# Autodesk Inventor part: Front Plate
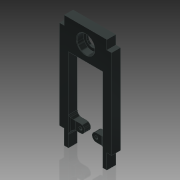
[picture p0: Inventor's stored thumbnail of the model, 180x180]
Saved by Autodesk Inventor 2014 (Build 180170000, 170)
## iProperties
Created: 2015-07
Part Number: Front Plate
Material: Generic
Document SubType Name: Modeling
Designer: Brad Factor
Density: 1 g/cm^3
Appearance: Gunmetal - Polished
Author: Brad Factor
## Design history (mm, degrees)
sketch "Sketch1"
  geometry: L1 (-8.509, 15.278)-(8.509, 15.278); L2 (-18.453, 83.414)-(18.453, 83.414); L3 (18.453, 83.414)-(18.453, 0); L4 (18.453, 0)-(27.978, 0); L5 (27.978, 0)-(27.978, 115.418); L6 (27.978, 115.418)-(-27.978, 115.418); L7 (-27.978, 115.418)-(-27.978, 0); L8 (-27.978, 0)-(-18.453, 0); L9 (-18.453, 0)-(-18.453, 83.414); L10 (-27.978, 109.068)-(27.978, 109.068); L11 (-27.978, 89.764)-(27.978, 89.764); C1 r 9.652 at (0, 99.416); C2 r 1.27 at (8.509, 15.278); C3 r 1.27 at (-8.509, 15.278); C4 r 9.588 at (0, 99.416); A1 r 12.103 centre (0, 15.278) between (0, 3.175) and (-12.103, 15.278); 3 further points
  constraints: 22 end point, 7 horizontal, 5 centre point, 5 point on line, 4 vertical, 3 horizontal alignment, 3 point on circle, 3 vertical alignment, 2 coincident, 2 tangent, 1 midpoint
  dimensions: "d0" = 24.2062 diameter of A1; "d1" = 3.175 distance of A1.start point (0, 0); "d2" = 19.304 diameter of C1; "d3" = 84.1375 distance of A1.centre C1.centre; "d4" = 2.54 diameter of C2; "d5" = 2.54 diameter of C3; "d6" = 17.018 distance of L1.end L1.start; "d7" = 6.35 distance from line of A1.end L9; "d8" = 6.35 distance from line of point (12.103, 15.278) L3; "d9" = 6.35 distance between parallel lines of L6 L10; "d10" = 6.35 distance between parallel lines of L11 L2; "d11" = 9.525 distance between parallel lines of L7 L9; "d12" = 9.525 distance between parallel lines of L5 L3; "d46" = 19.177 diameter of C4
extrude "Plate" new body sketch "Sketch1" distance "d13" = 9.525; taper "d14" = 0 deg
sketch "Sketch3"
  geometry: C1 r 9.588 at (0, 99.416); C2 r 6.413 at (0, 99.416); C3 r 9.588 at (0, 99.416) reference; 1 further point
  constraints: 2 centre point, 1 coincident, 1 concentric
  dimensions: "d47" = 3.175 radial gap between concentric circles of C1 C2
extrude "Bearing Flange" join sketch "Sketch3" distance "d20" = 2.38125; taper "d21" = 0 deg
sketch "Sketch4"
  geometry: L1 (18.453, 83.414)-(18.453, 0) reference; L2 (-18.453, 0)-(-18.453, 83.414) reference; L3 (-8.509, 19.723)-(-18.453, 19.723); L4 (-8.509, 10.833)-(-18.453, 10.833); L5 (-18.453, 10.833)-(-18.453, 19.723); L6 (18.453, 19.723)-(18.453, 10.833); L7 (18.453, 10.833)-(8.509, 10.833); L8 (8.509, 19.723)-(18.453, 19.723); C1 r 1.27 at (-8.509, 15.278) reference; C2 r 1.27 at (8.509, 15.278) reference; C3 r 3.2 at (0, 15.278); C4 r 6.413 at (0, 99.416) reference; A1 r 4.445 centre (-8.509, 15.278) between (-8.509, 10.833) and (-8.509, 19.723); A2 r 4.445 centre (8.509, 15.278) between (8.509, 19.723) and (8.509, 10.833); 2 further points
  constraints: 12 end point, 4 horizontal, 4 point on circle, 4 point on line, 4 tangent, 3 centre point, 3 coincident, 1 equal radius, 1 vertical
  dimensions: "d22" = 6.4008 diameter of C3; "d23" = 3.175 radial gap between concentric circles of C1 A1; "d45" = 84.1375 vertical distance of C4.centre C1.centre (derived)
extrude "Motor Mounting Flanges" join sketch "Sketch4" distance "d24" = 6.477; taper "d25" = 0 deg
sketch "Sketch5"
  geometry: L1 (8.509, 10.833)-(18.453, 10.833) reference; L2 (18.453, 19.723)-(18.453, 10.833) reference; L3 (18.453, 19.723)-(8.509, 19.723) reference; A1 r 4.445 centre (-8.509, 15.278) between (-8.509, 10.833) and (-8.509, 19.723) reference; A2 r 4.445 centre (8.509, 15.278) between (8.509, 19.723) and (8.509, 10.833) reference; 3 further points
  constraints: 2 coincident
hole "#4 Clearance Holes" sketch "Sketch5" at (-8.509, 15.278), (8.509, 15.278) diameter "d26" = 3.4544; stored, may be unused: countersink angle "d30" = 82 deg, drill point angle "d32" = 118 deg; dims "d27" = 19.05, "d28" = 5.5626, "d29" = 2.8448, "d31" = 25.4
fillet "3/16\" Fillets" dims "d33" = 4.7625
chamfer "20 mil Chamfer" distance "d34" = 0.508; stored, may be unused: second distance "d35" = 3.175, angle "d36" = 45 deg
sketch "Sketch6"
  geometry: L1 (27.978, 0)-(27.978, 115.418) reference; L2 (27.978, 115.418)-(-27.978, 115.418) reference; L3 (27.978, 115.418)-(22.962, 115.418); L4 (22.962, 115.418)-(22.962, 105.639); L5 (22.962, 105.639)-(27.978, 105.639); L6 (27.978, 105.639)-(27.978, 115.418); L7 (27.978, 0)-(22.962, 0); L8 (22.962, 0)-(22.962, 9.779); L9 (22.962, 9.779)-(27.978, 9.779); L10 (27.978, 9.779)-(27.978, 0); 1 further point
  constraints: 16 end point, 4 parallel, 2 horizontal, 2 perpendicular, 1 collinear, 1 point on line
  dimensions: "d37" = 5.0165 distance between parallel lines of L6 L4; "d38" = 5.0165 distance between parallel lines of L1 L8; "d39" = 9.779 distance of L3.end L4.end; "d40" = 9.779 distance of L7.end L8.end
extrude "Assembly Notches" cut sketch "Sketch6" stored distance "d41" = 5.08; taper "d42" = 0 deg
sketch "Sketch7"
  geometry: L1 (4.508, 0)-(4.508, 9.525) reference; L2 (0, 9.525)-(4.508, 9.525) reference; L3 (0, 9.525)-(4.508, 9.525); L4 (4.508, 9.525)-(4.508, 0); L5 (4.508, 0)-(0, 0); L6 (0, 0)-(0, 9.525); 1 further point
  constraints: 8 end point, 2 parallel, 1 horizontal, 1 perpendicular
extrude "Assembly Tab" join sketch "Sketch7" distance "d43" = 6.35; taper "d44" = 0 deg
mirror "Notch and Tab Mirror"
body "Solid1"
node "Projected Loop1"
